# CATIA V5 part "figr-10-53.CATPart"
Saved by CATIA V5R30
Part number: Part1
Bounding box of the stored display mesh (mm): x 0 to 100, y -43.492 to 31.468, z -3.623 to 11.497
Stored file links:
  D:\PROJECTS\CATIA V56R 2020\Resources\Parts File\c10_catia_v5_6r2020_prt\figr-10-53.CATPart
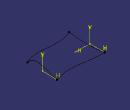
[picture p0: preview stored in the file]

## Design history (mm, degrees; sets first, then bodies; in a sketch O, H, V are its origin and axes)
Set1
  Sketch1 on yz-plane, origin (0, 0, 0), H (0, 1, 0), V (0, 0, 1)
  Plane1: type Offset, RefPlane yz-plane, Offset 100
  Sketch2 on xy-plane, origin (0, 0, 0), H (1, 0, 0), V (0, 1, 0)
    spline S1 through (0, 31.0443) (19.7053, 31.0443) (51.809, 26.4574) (100, 31.0443)
    reference intersected line E1 through (100, 0) direction (0, 1) from Plane1
    point P1 (0, 31.0443)
    point P2 (100, 31.0443)
    coincidence: P1 V, P2 E1
  Sketch3 on xy-plane, origin (0, 0, 0), H (1, 0, 0), V (0, 1, 0)
    spline S1 through (0, -43.492) (26.209, -36.2295) (80.3728, -38.1407) (100, -32.0249)
    reference intersected line E1 through (100, 0) direction (0, 1) from Plane1
    point P1 (0, -43.492)
    point P2 (100, -32.0249)
    coincidence: P1 V, P2 E1
  Sketch4 on Plane1, origin (100, 0, 0), H (0, 1, 0), V (0, 0, 1)
    spline S1 through (-32.0249, 0) (-14.5305, 11.3827) (11.9668, 5.3652) (31.0443, 0)
    reference projected point E1 (31.0443, 0) from vertex of Sketch2
    reference projected point E2 (-32.0249, 0) from vertex of Sketch3
    point P1 (-32.0249, 0)
    point P2 (31.0443, 0)
    coincidence: P1 H, P2 H, P2 E1, P1 E2
  Sketch5 on yz-plane, origin (0, 0, 0), H (0, 1, 0), V (0, 0, 1)
    spline S1 through (31.0443, 0) (7.4727, -3.1675) (-43.492, 0)
    reference projected point E1 (-43.492, 0) from vertex of Sketch3
    reference projected point E2 (31.0443, 0) from vertex of Sketch2
    point P1 (31.0443, 0)
    point P2 (-43.492, 0)
    coincidence: P1 H, P2 H, P2 E1, P1 E2
Body1 (main body)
